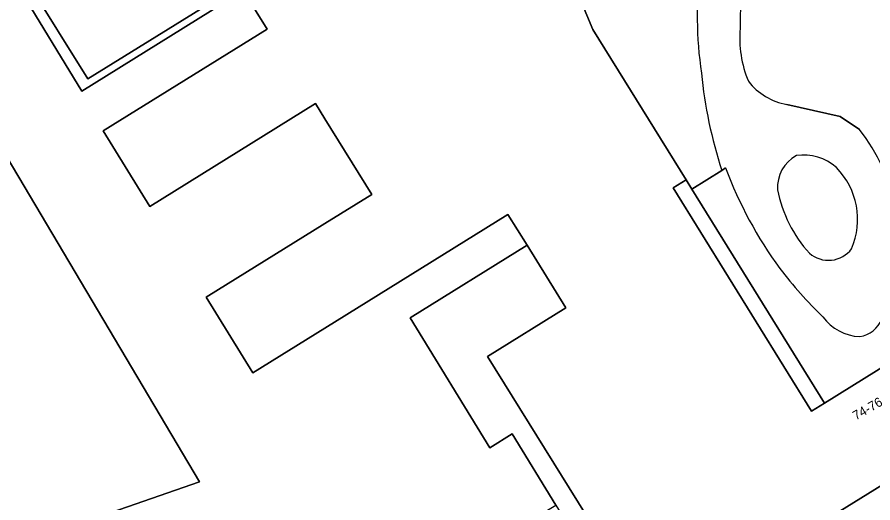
# Model space of a CAD drawing. Extents: x 158132 to 159664, y 385256 to 387218.
# Drawn here: x 158466.9 to 158558.9, y 386825.2 to 386877.4 of the extents above; entities that cross this region are included whole.
import ezdxf

# ---------------------------------------------------------------- set-up
doc = ezdxf.new("R2010")
doc.units = 0
for name, color, linetype in [('IMGEO_Berm_groen', 7, 'Continuous'), ('IMGEO_Gemengd_bos', 7, 'Continuous'), ('IMGEO_Grasland_overig', 7, 'Continuous'), ('IMGEO_Groenvoorziening', 7, 'Continuous'), ('IMGEO_Pand', 7, 'Continuous'), ('IMGEO_Pand_nummerreeks', 7, 'Continuous'), ('IMGEO_Pand_overbouw', 7, 'Continuous'), ('IMGEO_Rijbaan_lokaal_gesloten', 7, 'Continuous'), ('IMGEO_Voetpad_open', 7, 'Continuous')]:
    doc.layers.add(name, color=color, linetype=linetype)

msp = doc.modelspace()

# ---------------------------------------------------------------- linework, layer by layer
at = {"layer": 'IMGEO_Berm_groen'}
msp.add_lwpolyline([(158561.737, 386813.948), (158562.046, 386814.359), (158566.333, 386815.828), (158574.211, 386820.73), (158584.106, 386827.408), (158563.763, 386842.188), (158560.861, 386840.386), (158570.336, 386833.648), (158549.3, 386820.604), (158544.094, 386817.519), (158543.818, 386818.061), (158536.33, 386813.418), (158535.038, 386812.617), (158535.271, 386812.134), (158533.821, 386811.326), (158534.167, 386810.74)], dxfattribs=at)
at = {"layer": 'IMGEO_Gemengd_bos'}
msp.add_lwpolyline([(158357.846, 386741.184), (158369.81, 386745.156), (158383.657, 386750), (158412.171, 386759.975), (158418.535, 386762.109), (158408.094, 386792.273), (158405.756, 386799.458), (158486.517, 386827.494), (158458.512, 386874.593), (158467.121, 386880.528), (158468.04, 386881.162), (158474.303, 386885.046), (158473.334, 386886.61), (158478.552, 386889.845), (158478.05, 386890.654), (158500.86, 386902.127), (158502.096, 386899.985), (158504.702, 386901.302), (158514.744, 386905.783)], dxfattribs=at)
at = {"layer": 'IMGEO_Grasland_overig'}
for points in [[(158520.096, 386832.62), (158517.699, 386831.148), (158509.137, 386845.084), (158521.706, 386852.877), (158519.657, 386856.182), (158500, 386843.993), (158492.265, 386839.197), (158487.236, 386847.306), (158500, 386855.221), (158505.024, 386858.336), (158500, 386866.438), (158498.985, 386868.075), (158481.197, 386857.045), (158476.17, 386865.153), (158493.787, 386876.077), (158491.24, 386880.185), (158489.028, 386878.814), (158473.867, 386869.413), (158467.121, 386880.528), (158458.512, 386874.593), (158486.517, 386827.494), (158405.756, 386799.458)], [(158527.563, 386809.942), (158525.064, 386813.947), (158523.393, 386812.935), (158524.503, 386811.144), (158521.16, 386809.071), (158518.327, 386813.639), (158521.626, 386815.684), (158521.386, 386816.084), (158518.105, 386814.089), (158515.179, 386818.902), (158518.459, 386820.896), (158520.093, 386821.915), (158519.996, 386822.07), (158524.794, 386824.974), (158520.096, 386832.62)]]:
    msp.add_lwpolyline(points, dxfattribs=at)
at = {"layer": 'IMGEO_Groenvoorziening'}
for points in [[(158516.648, 386902.51), (158513.907, 386901.053), (158504.582, 386895.674), (158506.079, 386893.259), (158516.783, 386899.896), (158521.521, 386892.256), (158520.735, 386891.762), (158524.255, 386884.415), (158525.078, 386884.852), (158528.793, 386876.023), (158538.793, 386859.897), (158539.41, 386858.901), (158542.633, 386860.9)], [(158549.633, 386867.996), (158555.343, 386866.678), (158557.417, 386865.291)]]:
    msp.add_lwpolyline(points, dxfattribs=at)
for centre, radius, start, end in [((158579.507, 386877.307), 39.515, 171.96797, 188.68056), ((158587.421, 386876.531), 42.82, 172.2445, 180.50667), ((158556.651, 386875.121), 12.092, 175.11106, 202.59359), ((158588.723, 386876.007), 48.503, 185.51857, 198.14812), ((158550.73, 386874.535), 6.63, 217.74801, 260.47905), ((158542.619, 386853.436), 18.962, 341.89127, 38.69911), ((158552.522, 386859.077), 3.91, 118.78309, 183.68865), ((158551.414, 386857.287), 5.273, 47.98991, 98.43822), ((158549.307, 386855.642), 7.919, 336.65218, 44.63006), ((158562.421, 386861.492), 14.055, 190.93859, 222.35983), ((158554.081, 386854.39), 3.13, 229.17481, 322.91279)]:
    msp.add_arc(centre, radius, start, end, dxfattribs=at)
at = {"layer": 'IMGEO_Pand'}
msp.add_lwpolyline([(158482.131, 386889.899), (158479.522, 386888.282), (158478.552, 386889.845), (158473.334, 386886.61), (158474.303, 386885.046), (158468.04, 386881.162), (158474.511, 386870.726), (158488.602, 386879.463)], close=True, dxfattribs=at)
for points in [[(158560.861, 386840.386), (158553.66, 386835.92), (158552.282, 386835.065), (158537.415, 386859.042), (158538.793, 386859.897), (158528.793, 386876.023), (158525.078, 386884.852)], [(158491.24, 386880.185), (158493.787, 386876.077), (158476.17, 386865.153), (158481.197, 386857.045), (158498.985, 386868.075), (158500, 386866.438), (158505.024, 386858.336), (158500, 386855.221), (158487.236, 386847.306), (158492.265, 386839.197), (158500, 386843.993), (158519.657, 386856.182), (158521.706, 386852.877), (158525.878, 386846.148), (158517.477, 386840.939), (158528.043, 386823.899)], [(158549.3, 386820.604), (158570.336, 386833.648)]]:
    msp.add_lwpolyline(points, dxfattribs=at)
at = {"layer": 'IMGEO_Pand_overbouw'}
msp.add_lwpolyline([(158538.793, 386859.897), (158537.415, 386859.042), (158552.282, 386835.065), (158553.66, 386835.92)], close=True, dxfattribs=at)
at = {"layer": 'IMGEO_Rijbaan_lokaal_gesloten'}
for points in [[(158557.417, 386865.291), (158555.343, 386866.678), (158549.633, 386867.996)], [(158542.633, 386860.9), (158543.033, 386861.183)]]:
    msp.add_lwpolyline(points, dxfattribs=at)
for centre, radius, start, end in [((158579.507, 386877.307), 39.515, 171.96797, 188.68056), ((158587.421, 386876.531), 42.82, 172.2445, 180.50667), ((158556.651, 386875.121), 12.092, 175.11106, 202.59359), ((158588.723, 386876.007), 48.503, 185.51857, 198.14812), ((158550.73, 386874.535), 6.63, 217.74801, 260.47905), ((158542.619, 386853.436), 18.962, 341.89127, 38.69911), ((158552.522, 386859.077), 3.91, 118.78309, 183.68865), ((158551.414, 386857.287), 5.273, 47.98991, 98.43822), ((158585.13, 386876.957), 44.956, 200.54119, 216.24108), ((158549.307, 386855.642), 7.919, 336.65218, 44.63006), ((158562.421, 386861.492), 14.055, 190.93859, 222.35983), ((158554.081, 386854.39), 3.13, 229.17481, 322.91279), ((158585.79, 386878.611), 46.475, 217.40515, 225.97835), ((158557.609, 386848.153), 5.071, 215.73226, 268.17542), ((158557.005, 386846.068), 3.016, 278.44106, 338.37964)]:
    msp.add_arc(centre, radius, start, end, dxfattribs=at)
at = {"layer": 'IMGEO_Voetpad_open'}
for points in [[(158489.028, 386878.814), (158488.602, 386879.463), (158474.511, 386870.726), (158468.04, 386881.162), (158467.121, 386880.528), (158473.867, 386869.413)], [(158539.41, 386858.901), (158538.793, 386859.897), (158537.415, 386859.042), (158552.282, 386835.065), (158553.66, 386835.92)], [(158517.477, 386840.939), (158525.878, 386846.148), (158521.706, 386852.877), (158509.137, 386845.084), (158517.699, 386831.148), (158520.096, 386832.62), (158524.794, 386824.974), (158533.345, 386811.055), (158533.821, 386811.326), (158535.271, 386812.134), (158535.038, 386812.617), (158528.043, 386823.899)]]:
    msp.add_lwpolyline(points, close=True, dxfattribs=at)
msp.add_lwpolyline([(158543.033, 386861.183), (158542.633, 386860.9), (158539.41, 386858.901), (158553.66, 386835.92), (158560.861, 386840.386), (158563.763, 386842.188), (158584.106, 386827.408), (158584.424, 386827.177), (158585.2, 386826.613), (158585.515, 386826.384), (158586.757, 386825.482)], dxfattribs=at)
for centre, radius, start, end in [((158585.13, 386876.957), 44.956, 200.54119, 216.24108), ((158585.79, 386878.611), 46.475, 217.40515, 225.97835), ((158557.609, 386848.153), 5.071, 215.73226, 268.17542), ((158557.005, 386846.068), 3.016, 278.44106, 338.37964)]:
    msp.add_arc(centre, radius, start, end, dxfattribs=at)

# ---------------------------------------------------------------- texts
at = {"layer": 'IMGEO_Pand_nummerreeks'}
msp.add_text('74-76', height=1, rotation=29.9485, dxfattribs=at).set_placement((158557.04, 386834.055))

doc.saveas('drawing.dxf')
